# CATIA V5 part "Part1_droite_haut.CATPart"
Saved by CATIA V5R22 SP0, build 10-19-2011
Part number: Part1
Bounding box of the stored display mesh (mm): x 0 to 89.5, y -87.5 to 4.5, z 150 to 302
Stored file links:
  C:\Users\dussa\Documents\ENIB\S5\inter\Part1_droite_haut.CATPart
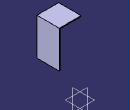
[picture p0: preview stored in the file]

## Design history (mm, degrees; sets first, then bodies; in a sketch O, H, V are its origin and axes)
Body1 (main body)
  Sketch1 on xy-plane, origin (0, 0, 0), H (1, 0, 0), V (0, 1, 0)
    line L1 (-87.5, 87.5) -> (87.5, 87.5)
    line L2 (87.5, 87.5) -> (87.5, -87.5)
    line L3 (87.5, -87.5) -> (-87.5, -87.5)
    line L4 (-87.5, -87.5) -> (-87.5, 87.5)
    distance L1 L3 = 175
    distance L4 L2 = 175
    horizontal: L1 H, L3 H
    vertical: L2 V, L4 V
    symmetry: L3 L1 H, L4 L2 V
  Pad1: profile Sketch1, direction (0, 0, 1), length 2
  Sketch2 on face of Pad1 from Sketch1.L2, origin (87.5, 0, 0), H (0, 1, 0), V (0, 0, 1)
    point P1 (-87.5, 0)
    line L1 (-87.5, 0) -> (87.5, 0)
    line L2 (87.5, 0) -> (87.5, 62.3217)
    line L3 (-87.5, 80) -> (-87.5, 0)
    point P3 (87.5, 62.3217)
    point P4 (-87.5, 80)
    reference projected line E1 (-87.5, 0) -> (-87.5, 2) from edge [face of Pad1 from Sketch1.L2 | face of Pad1 from Sketch1.L3]
    reference projected line E2 (87.5, 0) -> (87.5, 2) from edge [face of Pad1 from Sketch1.L1 | face of Pad1 from Sketch1.L2]
    reference projected line E3 (-87.5, 0) -> (87.5, 0) from edge [start face of Pad1 | face of Pad1 from Sketch1.L2]
    line L4 (-87.5, 300) -> (2.5, 300)
    line L5 (2.5, 300) -> (2.5, 115)
    line L6 (-87.5, 80) -> (-87.5, 300)
    point P8 (-87.5, 80)
    line L7 (2.5, 115) -> (87.5, 62.3217)
    point P9 (87.5, 62.3217)
    distance P4 P1 = 80
    distance L1 L4 = 300
    length L5 = 185
    distance L5 L6 = 90
    length L7 = 100
    horizontal: L1 H, L4 H
    vertical: L2 V, L3 V, L5 V, L6 V
    coincidence: E1 L3, L2 E2, L1 E3, L6 L3, P8 P4, L7 P3, P3 P9
  Pad2: profile Sketch2, direction (1, 0, 0), length 2
  Sketch3 on face of Pad1 from Sketch1.L4, origin (-87.5, 0, 0), H (0, 1, 0), V (0, 0, 1)
    point P1 (-87.5, 0)
    line L1 (-87.5, 0) -> (87.5, 0)
    line L2 (87.5, 0) -> (87.5, 62.3217)
    line L3 (-87.5, 80) -> (-87.5, 0)
    point P3 (87.5, 62.3217)
    point P4 (-87.5, 80)
    reference projected line E1 (-87.5, 0) -> (-87.5, 2) from edge [face of Pad1 from Sketch1.L2 | face of Pad1 from Sketch1.L3]
    reference projected line E2 (87.5, 0) -> (87.5, 2) from edge [face of Pad1 from Sketch1.L1 | face of Pad1 from Sketch1.L2]
    reference projected line E3 (-87.5, 0) -> (87.5, 0) from edge [start face of Pad1 | face of Pad1 from Sketch1.L2]
    line L4 (-87.5, 300) -> (2.5, 300)
    line L5 (2.5, 300) -> (2.5, 115)
    line L6 (-87.5, 80) -> (-87.5, 300)
    point P8 (-87.5, 80)
    line L7 (2.5, 115) -> (87.5, 62.3217)
    point P9 (87.5, 62.3217)
    distance P4 P1 = 80
    distance L1 L4 = 300
    length L5 = 185
    distance L5 L6 = 90
    length L7 = 100
    horizontal: L1 H, L4 H
    vertical: L2 V, L3 V, L5 V, L6 V
    coincidence: E1 L3, L2 E2, L1 E3, L6 L3, P8 P4, L7 P3, P3 P9
  Pad3: profile Sketch3, direction (1, 0, 0), length 2
  Sketch4 on face of Pad3 from Sketch3.L4, origin (0, 0, 300), H (1, 0, 0), V (0, 1, 0)
    line L1 (-87.5, 2.5) -> (89.5, 2.5)
    line L2 (89.5, 2.5) -> (89.5, -87.5)
    line L3 (89.5, -87.5) -> (-87.5, -87.5)
    line L4 (-87.5, -87.5) -> (-87.5, 2.5)
    reference projected line E1 (-87.5, -87.5) -> (87.5, -87.5) from edge [face of Pad3 | end face of Pad1]
    reference projected point E2 (89.5, 2.5) from vertex [face of Pad2 from Sketch2.L5 | face of Pad2 from Sketch2.L4 | end face of Pad2]
    reference projected line E3 (-87.5, 2.5) -> (-87.5, -87.5) from edge [start face of Pad3 | face of Pad3 from Sketch3.L4]
    reference projected line E4 (89.5, 2.5) -> (89.5, -87.5) from edge [face of Pad2 from Sketch2.L4 | end face of Pad2]
    horizontal: L1 H, L3 H
    vertical: L2 V, L4 V
    coincidence: L3 E1, L1 E2, L4 E3, E4 L2
  Pad4: profile Sketch4, direction (0, 0, 1), length 2
  Sketch5 on face of Pad3, origin (0, 87.5, 0), H (-1, 0, 0), V (0, 0, 1)
    line L1 (-89.5, 62.3217) -> (87.5, 62.3217)
    line L2 (87.5, 62.3217) -> (87.5, 0)
    line L3 (87.5, 0) -> (-89.5, 0)
    line L4 (-89.5, 0) -> (-89.5, 62.3217)
    reference projected point E1 (85.5, 62.3217) from vertex [end face of Pad3 | face of Pad3 from Sketch3.L2 | face of Pad3 from Sketch3.L7]
    reference projected line E2 (-87.5, 0) -> (87.5, 0) from edge [face of Pad3 | face of Pad3]
    reference projected line E3 (87.5, 0) -> (87.5, 2) from edge [face of Pad3 | face of Pad3]
    reference projected line E4 (-89.5, 0) -> (-89.5, 62.3217) from edge [face of Pad3 | end face of Pad2]
    horizontal: L1 H, L3 H
    vertical: L2 V, L4 V
    coincidence: E1 L1, E2 L3, L2 E3, E4 L4
  Pad5: profile Sketch5, direction (0, 1, 0), length 2
  Sketch6 on face of Pad2 from Sketch2.L7, origin (0, 52.1868, 84.2069), H (-1, 0, 0), V (0, -0.85, 0.5268)
    line L1 (-89.5, 58.455) -> (87.5, 58.455)
    line L2 (87.5, 58.455) -> (87.5, -43.245)
    line L3 (87.5, -43.245) -> (-89.5, -43.245)
    line L4 (-89.5, -43.245) -> (-89.5, 58.455)
    reference projected line E1 (87.5, -43.245) -> (-89.5, -43.245) from edge [face of Pad5 from Sketch5.L1 | end face of Pad5]
    reference projected line E2 (87.5, -41.545) -> (87.5, 58.455) from edge [face of Pad5 | face of Pad3 from Sketch3.L7]
    reference projected line E3 (87.5, 58.455) -> (85.5, 58.455) from edge [face of Pad3 from Sketch3.L5 | face of Pad3 from Sketch3.L7]
    reference projected line E4 (-89.5, -41.545) -> (-89.5, 58.455) from edge [face of Pad2 from Sketch2.L7 | face of Pad5]
    circle A1 centre (-50, 11.755) radius 14.5
    point P5 (-50, 11.755)
    circle A2 centre (50, 11.755) radius 3.35
    point P6 (50, 11.755)
    radius A1 = 14.5
    radius A2 = 3.35
    distance P5 V = 50
    distance P6 V = 50
    distance P5 L3 = 55
    distance P6 L3 = 55
    horizontal: L1 H, L3 H
    vertical: L2 V, L4 V
    coincidence: L3 E1, L2 E2, E3 L1, L4 E4
  Pad6: profile Sketch6, direction (0, 0.5268, 0.85), length 2
  Sketch7 on face of Pad3 from Sketch3.L5, origin (0, 2.5, 0), H (-1, 0, 0), V (0, 0, 1)
    line L1 (-89.5, 302) -> (87.5, 302)
    line L2 (87.5, 302) -> (87.5, 116.7)
    line L3 (87.5, 116.7) -> (-89.5, 116.7)
    line L4 (-89.5, 116.7) -> (-89.5, 302)
    reference projected line E1 (-89.5, 302) -> (87.5, 302) from edge [face of Pad4 from Sketch4.L1 | end face of Pad4]
    reference projected line E2 (87.5, 116.7) -> (-89.5, 116.7) from edge [face of Pad6 from Sketch6.L1 | end face of Pad6]
    reference projected line E3 (-89.5, 115) -> (-89.5, 300) from edge [face of Pad2 from Sketch2.L5 | face of Pad6]
    reference projected line E4 (87.5, 115) -> (87.5, 300) from edge [face of Pad6 | face of Pad3 from Sketch3.L5]
    line L5 (-86, 298.5) -> (84, 298.5)
    line L6 (84, 298.5) -> (84, 128.5)
    line L7 (84, 128.5) -> (-86, 128.5)
    line L8 (-86, 128.5) -> (-86, 298.5)
    distance L6 L8 = 170
    distance L5 L7 = 170
    distance L5 L1 = 3.5
    distance L8 L4 = 3.5
    horizontal: L1 H, L3 H, L5 H, L7 H
    vertical: L2 V, L4 V, L6 V, L8 V
    coincidence: L1 E1, L3 E2, L4 E3, L2 E4
  Pad7: profile Sketch7, direction (0, 1, 0), length 2
  Split1: SplitPlane yz-plane
  Split2: SplitPlane {plane type Offset, RefPlane xy-plane, Offset 150}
